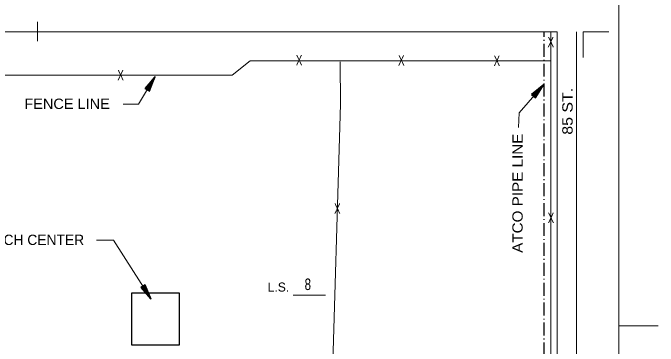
# Model space of a CAD drawing. Extents: x -496 to 480, y -450 to 700.
# Drawn here: x -19 to 480.3, y 159.3 to 416.9 of the extents above; entities that cross this region are included whole.
import ezdxf
from ezdxf.enums import TextEntityAlignment as Align

# ---------------------------------------------------------------- set-up
doc = ezdxf.new("R2010")
doc.units = 0
doc.header["$LTSCALE"] = 2
doc.linetypes.add('DOT_DASHED', pattern=[7.7, 5, -1.2, 0.3, -1.2])
for name, color, linetype, lineweight in [('1', 7, 'Continuous', 13), ('3', 7, 'Continuous', 13), ('4', 7, 'Continuous', 25)]:
    doc.layers.add(name, color=color, linetype=linetype, lineweight=lineweight)

msp = doc.modelspace()

# ---------------------------------------------------------------- linework, layer by layer
at = {"layer": '1'}
for p, q in [((-0.017, 394.973), (-0.017, 409.973)), ((422.281, 402.339), (442.281, 402.339)), ((422.281, 402.339), (422.281, 382.339)), ((198.019, 198.738), (223.019, 198.738)), ((480.331, 174.973), (449.983, 174.973))]:
    msp.add_line(p, q, dxfattribs=at)
for points in [[(449.983, -450.027), (449.983, 399.973), (449.983, 699.973), (-450.017, 699.973), (-450.017, 49.973), (-450.017, -450.027)], [(402.281, -402.333), (402.281, 402.339), (-402.391, 402.339)]]:
    msp.add_lwpolyline(points, dxfattribs=at)
at = {"layer": '3', "linetype": 'DOT_DASHED', "lineweight": 25}
msp.add_line((392.281, -402.333), (392.281, 402.339), dxfattribs=at)
at = {"layer": '3'}
for p, q in [((397.281, -58.045), (397.281, 402.339)), ((417.281, -253.126), (417.281, 402.339)), ((164.621, 379.989), (150.641, 368.814))]:
    msp.add_line(p, q, dxfattribs=at)
for points in [[(397.281, 379.989), (164.621, 379.989), (150.641, 368.814), (-31.099, 368.814)], [(397.281, -58.045), (206.561, -11.136), (227.531, 111.789), (234.521, 346.464), (234.183, 379.125)]]:
    msp.add_lwpolyline(points, dxfattribs=at)
at = {"layer": '3', "lineweight": 25}
msp.add_lwpolyline([(72.777, 160.191), (109.909, 160.191), (109.909, 200.189), (72.777, 200.189)], close=True, dxfattribs=at)
at = {"layer": '4', "lineweight": 13}
for points in [[(66.398, 346.389), (78.203, 346.389), (91.107, 367.779)], [(372.371, 328.215), (372.69, 339.658), (391.784, 361.59)], [(45.838, 241.277), (58.944, 241.277), (88.067, 195.462)]]:
    msp.add_lwpolyline(points, dxfattribs=at)
at = {"layer": '4'}
for points in [[(91.107, 367.779), (83.196, 358.537), (86.621, 356.471)], [(391.784, 361.59), (382.396, 353.853), (385.413, 351.226)], [(88.067, 195.462), (83.317, 206.662), (79.942, 204.516)]]:
    msp.add_lwpolyline(points, close=True, dxfattribs=at)
for points in [[(83.348, 358.56), (90.81, 367.288), (86.564, 356.695), (83.519, 358.507), (90.429, 366.657), (86.518, 356.95), (83.737, 358.576), (90.027, 365.991), (86.432, 357.229), (83.988, 358.576), (89.553, 365.244), (86.389, 357.534), (84.287, 358.65), (88.985, 364.348), (86.267, 357.835), (84.621, 358.701), (88.376, 363.379), (86.134, 358.242), (84.957, 358.801), (87.672, 362.337), (86.09, 358.671), (85.346, 358.944), (86.919, 361.049), (85.978, 359.193)], [(382.549, 353.849), (391.406, 361.158), (385.396, 351.457), (382.709, 353.768), (390.923, 360.603), (385.394, 351.716), (382.935, 353.798), (390.412, 360.016), (385.358, 352.006), (383.183, 353.755), (389.815, 359.362), (385.368, 352.314), (383.49, 353.776), (389.101, 358.577), (385.3, 352.631), (383.827, 353.768), (388.334, 357.728), (385.239, 353.055), (384.176, 353.809), (387.461, 356.824), (385.27, 353.486), (384.584, 353.883), (386.497, 355.685), (385.25, 354.019)], [(83.27, 206.516), (87.76, 195.946), (80.167, 204.467), (83.147, 206.385), (87.365, 196.568), (80.416, 204.394), (83.112, 206.16), (86.947, 197.225), (80.705, 204.347), (83, 205.935), (86.49, 197.983), (80.997, 204.25), (82.933, 205.634), (85.941, 198.891), (81.32, 204.225), (82.829, 205.313), (85.344, 199.867), (81.744, 204.163), (82.769, 204.968), (84.726, 200.962), (82.148, 204.011), (82.724, 204.555), (83.908, 202.209), (82.666, 203.878)]]:
    msp.add_lwpolyline(points, dxfattribs=at)

# ---------------------------------------------------------------- texts
at = {"layer": '1', "width": 0.75}
msp.add_text('8', height=8.89, dxfattribs=at).set_placement((209.262, 202.642), align=Align.CENTER)
at = {"layer": '1'}
msp.add_text('L.S.', height=7, dxfattribs=at).set_placement((186.537, 201.437), align=Align.CENTER)
at = {"layer": '3', "width": 0.7}
for p in [(397.3, 390.43), (202.491, 376.328), (281.608, 376.242), (355.555, 375.903), (64.365, 364.803), (232.093, 261.571), (397.417, 254.355)]:
    msp.add_text('X', height=8, dxfattribs=at).set_placement(p, align=Align.CENTER)
at = {"layer": '4'}
for s, width, p in [('85 ST.', 1.15, (414.19, 340.878)), ('ATCO PIPE LINE', 1.1, (375.557, 277.499))]:
    msp.add_text(s, height=8, rotation=90, dxfattribs=dict(at, width=width)).set_placement(p, align=Align.CENTER)
at = {"layer": '4', "width": 1.05}
msp.add_text('FENCE LINE', height=8, dxfattribs=at).set_placement((22.945, 342.652), align=Align.CENTER)
at = {"layer": '4'}
msp.add_text('RESEARCH CENTER', height=8, dxfattribs=at).set_placement((-17.025, 237.444), align=Align.CENTER)

doc.saveas('drawing.dxf')
